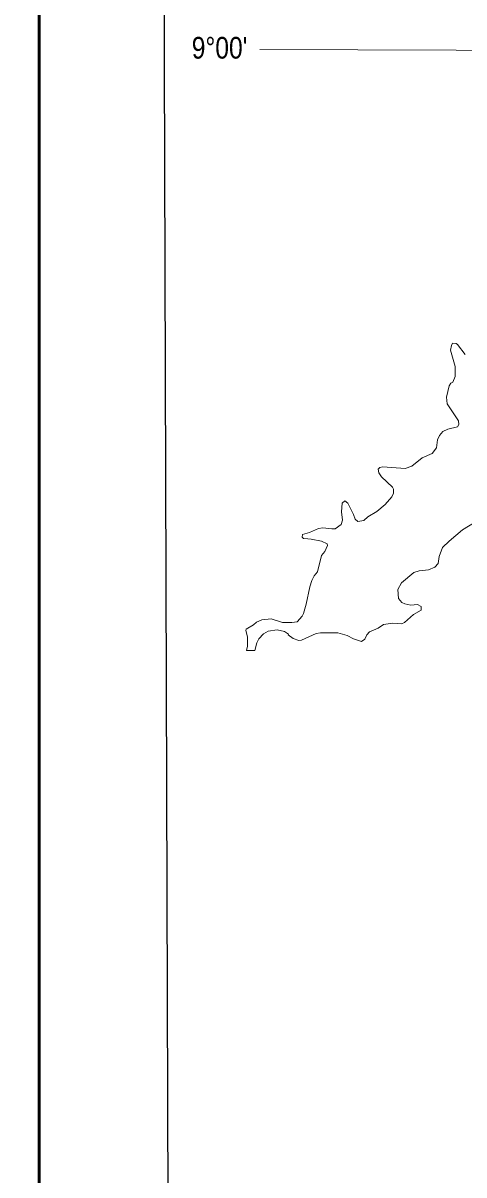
# Model space of a CAD drawing. Extents: x -1643653 to 4543381, y 1624270 to 13878484.
# Drawn here: x 559837 to 570009, y 8979171 to 9005760 of the extents above; entities that cross this region are included whole.
import ezdxf
from ezdxf.enums import TextEntityAlignment as Align

# ---------------------------------------------------------------- set-up
doc = ezdxf.new("R2010")
doc.units = 0
doc.header["$LTSCALE"] = 200
for name, color, linetype, lineweight in [('1', 7, 'Continuous', 13), ('25', 7, 'Continuous', 13), ('3', 7, 'Continuous', 13), ('60', 7, 'Continuous', 13)]:
    doc.layers.add(name, color=color, linetype=linetype, lineweight=lineweight)
doc.layers.add('46', color=7, linetype='Continuous')

msp = doc.modelspace()

# ---------------------------------------------------------------- linework, layer by layer
at = {"layer": '1'}
msp.add_lwpolyline([(565303.2, 9005146.6), (664889.8, 9004806.7), (719872.1, 9004543.9), (790635.8, 9004109)], dxfattribs=at)
at = {"layer": '25'}
for points in [[(570039.3, 8998110.8), (569862.2, 8998339.7), (569828.8, 8998363.9), (569747.5, 8998367.9), (569719.3, 8998318.1), (569695.6, 8998210), (569803.5, 8997832.4), (569805.7, 8997600.4), (569753.7, 8997466.5), (569708.6, 8997447), (569671.8, 8997384.4), (569607, 8997125.3), (569624.2, 8996969.4), (569883.5, 8996580.5), (569890, 8996489.7), (569862.1, 8996442.2), (569634.2, 8996387.6), (569524.8, 8996331.6), (569444.9, 8996241), (569401.6, 8996135.2), (569377.7, 8995955.6), (569276.2, 8995821.7), (569042.7, 8995719.9), (568806.8, 8995531.7), (568653.5, 8995475.6), (568134.7, 8995512.3), (568072.2, 8995501.6), (568030.8, 8995462.5), (568041.7, 8995378.5), (568108.6, 8995287.8), (568364, 8995043), (568387.6, 8994997.6), (568385.5, 8994911.7), (568342.3, 8994825.1), (568190.7, 8994643.1), (567996.1, 8994487.5), (567788.8, 8994357.9), (567698, 8994275.9), (567560, 8994252.1), (567499.2, 8994304.1), (567462.2, 8994418.7), (567330.6, 8994677.7), (567263.6, 8994734), (567200.7, 8994675.1), (567183.6, 8994478), (567209.4, 8994288.5), (567174.9, 8994185.2), (567041.5, 8994087.6), (566962.8, 8994081.3), (566755.8, 8994109.3), (566652.7, 8994094.4), (566443.9, 8994001.2), (566287.2, 8993950.5), (566277.5, 8993895.3), (566309.1, 8993863.6), (566406.3, 8993853.8)], [(570039.3, 8998110.8), (569862.2, 8998339.7), (569828.8, 8998363.9), (569747.5, 8998367.9), (569719.3, 8998318.1), (569695.6, 8998210), (569803.5, 8997832.4), (569805.7, 8997600.4), (569753.7, 8997466.5), (569708.6, 8997447), (569671.8, 8997384.4), (569607, 8997125.3), (569624.2, 8996969.4), (569883.5, 8996580.5), (569890, 8996489.7), (569862.1, 8996442.2), (569634.2, 8996387.6), (569524.8, 8996331.6), (569444.9, 8996241), (569401.6, 8996135.2), (569377.7, 8995955.6), (569276.2, 8995821.7), (569042.7, 8995719.9), (568806.8, 8995531.7), (568653.5, 8995475.6), (568134.7, 8995512.3), (568072.2, 8995501.6), (568030.8, 8995462.5), (568041.7, 8995378.5), (568108.6, 8995287.8), (568364, 8995043), (568387.6, 8994997.6), (568385.5, 8994911.7), (568342.3, 8994825.1), (568190.7, 8994643.1), (567996.1, 8994487.5), (567788.8, 8994357.9), (567698, 8994275.9), (567560, 8994252.1), (567499.2, 8994304.1), (567462.2, 8994418.7), (567330.6, 8994677.7), (567263.6, 8994734), (567200.7, 8994675.1), (567183.6, 8994478), (567209.4, 8994288.5), (567174.9, 8994185.2), (567041.5, 8994087.6), (566962.8, 8994081.3), (566755.8, 8994109.3), (566652.7, 8994094.4), (566443.9, 8994001.2), (566287.2, 8993950.5), (566277.5, 8993895.3), (566309.1, 8993863.6), (566406.3, 8993853.8)], [(568487.1, 8992684.5), (568569.1, 8992838), (568854.8, 8993074), (568977.6, 8993117), (569194, 8993136.6), (569341.2, 8993199.5), (569413.7, 8993286.4), (569438.4, 8993446), (569516.9, 8993653.7), (569666.9, 8993803.6), (569976.6, 8994064), (570432.9, 8994338.6)], [(568487.1, 8992684.5), (568569.1, 8992838), (568854.8, 8993074), (568977.6, 8993117), (569194, 8993136.6), (569341.2, 8993199.5), (569413.7, 8993286.4), (569438.4, 8993446), (569516.9, 8993653.7), (569666.9, 8993803.6), (569976.6, 8994064), (570432.9, 8994338.6)], [(566406.3, 8993853.8), (566487.5, 8993845.6), (566720.4, 8993798.2), (566856.8, 8993741.9), (566861.3, 8993701.1), (566803.3, 8993560.8), (566725.3, 8993467.3), (566628, 8993095.8), (566556.6, 8993002.5), (566500.5, 8992892.5), (566452.8, 8992749.4), (566371.7, 8992344.8), (566307.9, 8992133.6), (566273.3, 8992070.6), (566159, 8991941.3), (566037.8, 8991923.8), (565822.3, 8991921.6), (565557.9, 8992003.8), (565347.2, 8991985.1), (565224.8, 8991932.3), (565151.5, 8991872), (564980.8, 8991770.3), (564976.4, 8991740.3), (564976.4, 8991740.3), (565017.4, 8991591.1), (565017.4, 8991374.7), (564994.9, 8991274.5), (565186.5, 8991274.5)], [(566406.3, 8993853.8), (566487.5, 8993845.6), (566720.4, 8993798.2), (566856.8, 8993741.9), (566861.3, 8993701.1), (566803.3, 8993560.8), (566725.3, 8993467.3), (566628, 8993095.8), (566556.6, 8993002.5), (566500.5, 8992892.5), (566452.8, 8992749.4), (566371.7, 8992344.8), (566307.9, 8992133.6), (566273.3, 8992070.6), (566159, 8991941.3), (566037.8, 8991923.8), (565822.3, 8991921.6), (565557.9, 8992003.8), (565347.2, 8991985.1), (565224.8, 8991932.3), (565151.5, 8991872), (564980.8, 8991770.3), (564976.4, 8991740.3), (564976.4, 8991740.3), (565017.4, 8991591.1), (565017.4, 8991374.7), (564994.9, 8991274.5), (565186.5, 8991274.5)], [(565186.5, 8991274.5), (565229.4, 8991456.8), (565277, 8991543.6), (565385, 8991662.2), (565495.2, 8991724.9), (565699.6, 8991750.3), (565868.8, 8991714.1), (565962.8, 8991656.3), (565956, 8991638.4), (566069.6, 8991550.2), (566202.1, 8991510.9), (566262.2, 8991518.1), (566602.6, 8991670.9), (566699.3, 8991686), (567101.1, 8991683.8), (567313.2, 8991623.3), (567457.9, 8991543.5), (567647.8, 8991487.2), (567719.8, 8991534.9), (567767.4, 8991634.3), (567827.8, 8991705.4), (568027.3, 8991790.1), (568156.3, 8991874), (568371.7, 8991906.5), (568571.6, 8991889.4), (568638.4, 8991921.7), (568847.5, 8992104.9), (569018.9, 8992209.7), (569025.4, 8992289.9), (568938.9, 8992336.7), (568783.5, 8992319.5), (568643, 8992349.7), (568576.9, 8992385), (568495.8, 8992479.4), (568487.1, 8992684.5)], [(565186.5, 8991274.5), (565229.4, 8991456.8), (565277, 8991543.6), (565385, 8991662.2), (565495.2, 8991724.9), (565699.6, 8991750.3), (565868.8, 8991714.1), (565962.8, 8991656.3), (565956, 8991638.4), (566069.6, 8991550.2), (566202.1, 8991510.9), (566262.2, 8991518.1), (566602.6, 8991670.9), (566699.3, 8991686), (567101.1, 8991683.8), (567313.2, 8991623.3), (567457.9, 8991543.5), (567647.8, 8991487.2), (567719.8, 8991534.9), (567767.4, 8991634.3), (567827.8, 8991705.4), (568027.3, 8991790.1), (568156.3, 8991874), (568371.7, 8991906.5), (568571.6, 8991889.4), (568638.4, 8991921.7), (568847.5, 8992104.9), (569018.9, 8992209.7), (569025.4, 8992289.9), (568938.9, 8992336.7), (568783.5, 8992319.5), (568643, 8992349.7), (568576.9, 8992385), (568495.8, 8992479.4), (568487.1, 8992684.5)]]:
    msp.add_lwpolyline(points, dxfattribs=at)
at = {"layer": '3', "lineweight": 53}
msp.add_lwpolyline([(840307.3, 9029887.8), (840307.3, 8886387.8), (560211.7, 8886387.8), (560211.7, 9029887.8)], close=True, dxfattribs=at)
msp.add_lwpolyline([(840307.3, 9029887.8), (840307.3, 8886387.8), (560211.7, 8886387.8), (560211.7, 9029887.8)], close=True, dxfattribs=at)
at = {"layer": '3', "lineweight": 25}
msp.add_lwpolyline([(563033.9, 9026438.8), (793061.1, 9026438.8), (793495.6, 8889836.8), (563468.3, 8889836.8)], close=True, dxfattribs=at)
at = {"layer": '60', "lineweight": 25}
msp.add_spline([(814781, 9009175.5), (814787.2, 9009173.4), (814796.9, 9009173.4), (814799.4, 9009172.4), (814805.1, 9009174.5), (814805.6, 9009176.5), (814811.7, 9009179.5), (814811.7, 9009179.5), (814801.5, 9009181), (814790.7, 9009181.5), (814784.1, 9009183.1), (814777.4, 9009185.1), (814778.4, 9009175.5)], degree=3, dxfattribs=at)

# ---------------------------------------------------------------- texts
at = {"layer": '46', "width": 0.85}
msp.add_text("9°00'", height=500, dxfattribs=at).set_placement((564370.9, 9004939.3), align=Align.CENTER)

doc.saveas('drawing.dxf')
